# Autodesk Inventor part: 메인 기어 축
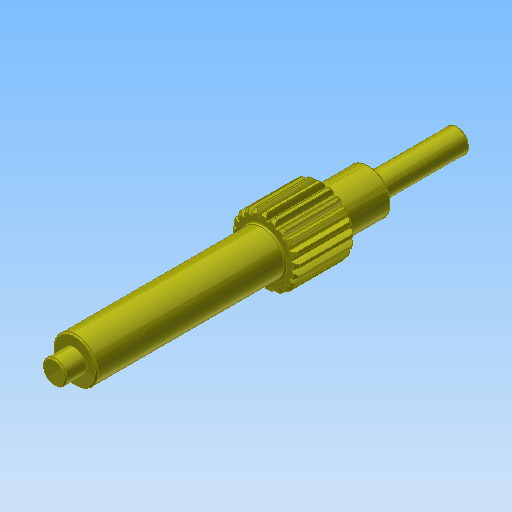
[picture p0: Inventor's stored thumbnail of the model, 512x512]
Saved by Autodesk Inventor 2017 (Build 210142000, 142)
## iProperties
Created: 2018-12
Part Number: 메인 기어 축
Material: 강철, 연강
Document SubType Name: Modeling
Designer: mduedu
Categories: <?xml version="1.0" encoding="UTF-16"?> <MemberInstance><Categories><FamilyTemplate><FamilyTemplateParameter ValueType="xs:double" Id="1" ObjectReferenceKey="da
Density: 7.86 g/cm^3
Appearance: 노란색
Mass: 179.676 g
Surface Area: 75.4119 cm^2
Volume: 22.8595 cm^3
CustomPartVersion: 1
Author: mduedu
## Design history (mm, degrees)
sketch "Sketch1"
  geometry: C1 r 11.3 at (0, 0)
  constraints: 1 centre point
  dimensions: "d0" = 22.6 diameter of C1 (= da_da)
extrude "Extrusion1" new body sketch "Sketch1" distance "d1" = 20 (= da_b); taper "d2" = 0 deg
workplane "Work Plane2"
sketch "Sketch2"
  geometry: C1 r 11.3 at (0, 0) reference; C2 r 10.5 at (0, 0)
  constraints: 1 centre point, 1 coincident
  dimensions: "d3" = 21 diameter of C2 (= da_dw)
feature "피치 지름" sketch "Sketch2" dims "d4" = 10, "d5" = 0
workplane "Work Plane8"
workplane "Work Plane9"
chamfer "모따기1" distance "d49" = 1; stored, may be unused: second distance "d50" = 2, angle "d51" = 45 deg
sketch "스케치3"
  geometry: C1 r 7.5 at (0, 0); 1 further point
  constraints: 1 centre point, 1 coincident
  dimensions: "d52" = 15 diameter of C1
extrude "돌출2" join sketch "스케치3" distance "d53" = 64; taper "d54" = 0 deg
sketch "스케치4"
  geometry: C1 r 4 at (0, 0); 1 further point
  constraints: 1 centre point, 1 coincident
  dimensions: "d55" = 8 diameter of C1
extrude "돌출3" join sketch "스케치4" distance "d56" = 7; taper "d57" = 0 deg
sketch "스케치5"
  geometry: C1 r 7.5 at (0, 0) reference; C2 r 7.5 at (0, 0) reference; 1 further point
extrude "돌출4" join sketch "스케치5" distance "d58" = 16; taper "d59" = 0 deg
sketch "스케치6"
  geometry: C1 r 4 at (0, 0); 1 further point
  constraints: 1 centre point, 1 coincident
  dimensions: "d60" = 8 diameter of C1
extrude "돌출5" join sketch "스케치6" distance "d61" = 30; taper "d62" = 0 deg
chamfer "모따기2" distance "d63" = 0.5; stored, may be unused: second distance "d64" = 2, angle "d65" = 45 deg
fillet "모깎기1" dims "d66" = 0.5
feature "스퍼 기어" dims "d39" = 0, "da_b" = 20, "da_d" = 21, "da_aw" = 31, "da_da" = 22.6, "da_df" = 19.086, "da_dw" = 21, angle "da_beta" = 0 deg, "da_lefttooth" = 0, "da_righttooth" = 0
sketch "스케치7" dims "d67" = 18
  geometry: C1 r 0.25 at (0, -9); 2 further points
  constraints: 2 vertical alignment, 1 centre point, 1 coincident, 2 other
  dimensions: "d68" = 0.5 diameter of C1
extrude "돌출6" join sketch "스케치7" distance "d69" = 0.3; taper "d70" = 0 deg
body "Solid1"
body "Srf1"
node "투영된 루프1"
other parameters: "d16" = 31 (= da_aw), "d17" = 0, "d34" = 1.496 (computed from da_z), "d41" = 0, "d43" = 31 (= da_aw), "d46" = 31 (= da_aw), "d47" = 0, "d48" = 0
